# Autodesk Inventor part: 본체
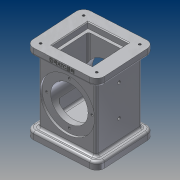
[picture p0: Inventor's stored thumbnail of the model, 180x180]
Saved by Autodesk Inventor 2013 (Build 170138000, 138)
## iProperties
Created: 2017-08
Part Number: 본체
Material: 알루미늄 6061
Document SubType Name: Modeling
Designer: Windows7
Mass: 872.324 g
Surface Area: 642.248 cm^2
Volume: 321.891 cm^3
Density: 2.71 g/cm^3
Author: Windows7
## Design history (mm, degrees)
sketch "스케치1"
  geometry: L1 (-36, 41)-(36, 41); L2 (46, 31)-(46, -31); L3 (36, -41)-(-36, -41); L4 (-46, -31)-(-46, 31); A1 r 10 centre (-36, 31) between (-36, 41) and (-46, 31); A2 r 10 centre (36, 31) between (46, 31) and (36, 41); A3 r 10 centre (36, -31) between (36, -41) and (46, -31); A4 r 10 centre (-36, -31) between (-46, -31) and (-36, -41); 7 further points
  constraints: 8 end point, 8 point on circle, 8 point on line, 8 tangent, 4 centre point, 3 equal radius, 2 midpoint, 2 parallel, 1 horizontal, 1 horizontal alignment, 1 perpendicular, 1 vertical alignment
  dimensions: "d60" = 10 radius of A1; "d61" = 92 distance between parallel lines of L2 L4; "d62" = 82 distance between parallel lines of L3 L1
extrude "돌출1" new body sketch "스케치1" distance "d3" = 10; taper "d4" = 0 deg
sketch "스케치2"
  geometry: L1 (-37, 33)-(37, 33); L2 (37, 33)-(37, -33); L3 (37, -33)-(-37, -33); L4 (-37, -33)-(-37, 33); 3 further points
  constraints: 8 end point, 2 midpoint, 2 parallel, 1 horizontal, 1 horizontal alignment, 1 perpendicular, 1 vertical alignment
  dimensions: "d5" = 74 distance of L1.start L1.end; "d7" = 66 distance of L3.end L1.start
extrude "돌출2" join sketch "스케치2" distance "d8" = 88; taper "d9" = 0 deg
node "작업 평면1"
sketch "스케치3"
  geometry: L1 (-24, 24)-(24, 24); L2 (24, 24)-(24, -24); L3 (24, -24)-(-24, -24); L4 (-24, -24)-(-24, 24); 3 further points
  constraints: 8 end point, 2 midpoint, 2 parallel, 2 perpendicular, 1 horizontal, 1 horizontal alignment, 1 vertical alignment
  dimensions: "d11" = 48 distance of L1.start L1.end
extrude "돌출3" cut sketch "스케치3" distance "d13" = 16; taper "d14" = 0 deg
sketch "스케치6"
  geometry: 2 further points
  constraints: 1 vertical alignment
  dimensions: "d23" = 54 distance of point (37, -44) point (37, 10)
hole "구멍1" sketch "스케치6" at (37, -44) diameter "d24" = 48; stored, may be unused: countersink angle "d28" = 90 deg, drill point angle "d30" = 118 deg; dims "d25" = 6, "d26" = 70, "d27" = 3, "d29" = 8
hole "구멍2" diameter "d33" = 48; stored, may be unused: countersink angle "d37" = 90 deg, drill point angle "d39" = 118 deg; dims "d31" = 10, "d32" = 10, "d34" = 6, "d35" = 70, "d36" = 3, "d38" = 8
sketch "스케치7"
  geometry: L1 (24, -19)-(68, -19); L2 (68, -19)-(68, -63); L3 (68, -63)-(24, -63); L4 (24, -63)-(24, -19); 3 further points
  constraints: 8 end point, 2 midpoint, 2 parallel, 2 perpendicular, 1 horizontal, 1 horizontal alignment, 1 vertical alignment
  dimensions: "d40" = 44 distance of L1.start L1.end
extrude "돌출6" cut sketch "스케치7" distance "d42" = 82; taper "d43" = 0 deg
sketch "스케치8"
  geometry: L1 (24, -63)-(24, -19) reference; L2 (24, -19)-(68, -19) reference; L3 (68, -19)-(68, -63) reference; L4 (68, -63)-(24, -63) reference; L5 (20, -15)-(72, -15); L6 (72, -15)-(72, -67); L7 (72, -67)-(20, -67); L8 (20, -67)-(20, -15); 3 further points
  constraints: 8 end point, 2 midpoint, 2 parallel, 2 perpendicular, 1 horizontal, 1 horizontal alignment, 1 vertical alignment
  dimensions: "d44" = 52 distance of L5.start L5.end
extrude "돌출7" cut sketch "스케치8" distance "d46" = 8; taper "d47" = 0 deg
sketch "스케치9" dims "d48" = 58
  geometry: C1 r 35 at (0, 0) reference; C2 r 24 at (0, 0) reference; 3 further points
  constraints: 2 vertical alignment, 1 coincident, 2 other
hole "구멍3" sketch "스케치9" at (0, 29) diameter "d50" = 3.242; stored, may be unused: countersink angle "d54" = 90 deg, drill point angle "d56" = 118 deg; dims "d51" = 4, "d52" = 70, "d53" = 3, "d55" = 6
hole "구멍4" diameter "d65" = 3.242; stored, may be unused: countersink angle "d69" = 90 deg, drill point angle "d71" = 118 deg; dims "d63" = 10, "d64" = 10, "d66" = 4, "d67" = 70, "d68" = 3, "d70" = 6
node "작업 평면2"
sketch "스케치10"
  geometry: 3 further points
  constraints: 2 horizontal alignment
  dimensions: "d79" = 38 distance of point (28, 33) point (-10, 33); "d80" = 42 distance of point (70, 33) point (28, 33)
hole "구멍5" sketch "스케치10" at (28, 33), (70, 33) diameter "d81" = 4.134; stored, may be unused: countersink angle "d85" = 90 deg, drill point angle "d87" = 118 deg; dims "d82" = 20, "d83" = 70, "d84" = 3, "d86" = 30
fillet "모깎기1" dims "d88" = 3
fillet "모깎기2" dims "d89" = 3
fillet "모깎기3" dims "d90" = 3
fillet "모깎기4" dims "d91" = 3
fillet "모깎기5" dims "d92" = 3
fillet "모깎기6" dims "d93" = 3
chamfer "모따기1" distance "d94" = 1; stored, may be unused: second distance "d95" = 2, angle "d96" = 45 deg
sketch "스케치11"
  geometry: 2 further points
  constraints: 1 other
feature "엠보싱1" sketch "스케치11" dims "d11" = 48, "d60" = 10, "d61" = 92, "d62" = 82, "d97" = 0.5, "d98" = 0
node "솔리드1"
mirror "대칭1"
pattern_circular "원형 패턴1" dims angle "d58" = 360 deg
mirror "대칭2"
pattern_linear "직사각형 패턴1" dims "d74" = 72, "d77" = 62
mirror "대칭3"
other parameters: "d10" = 54, "d78" = -54
